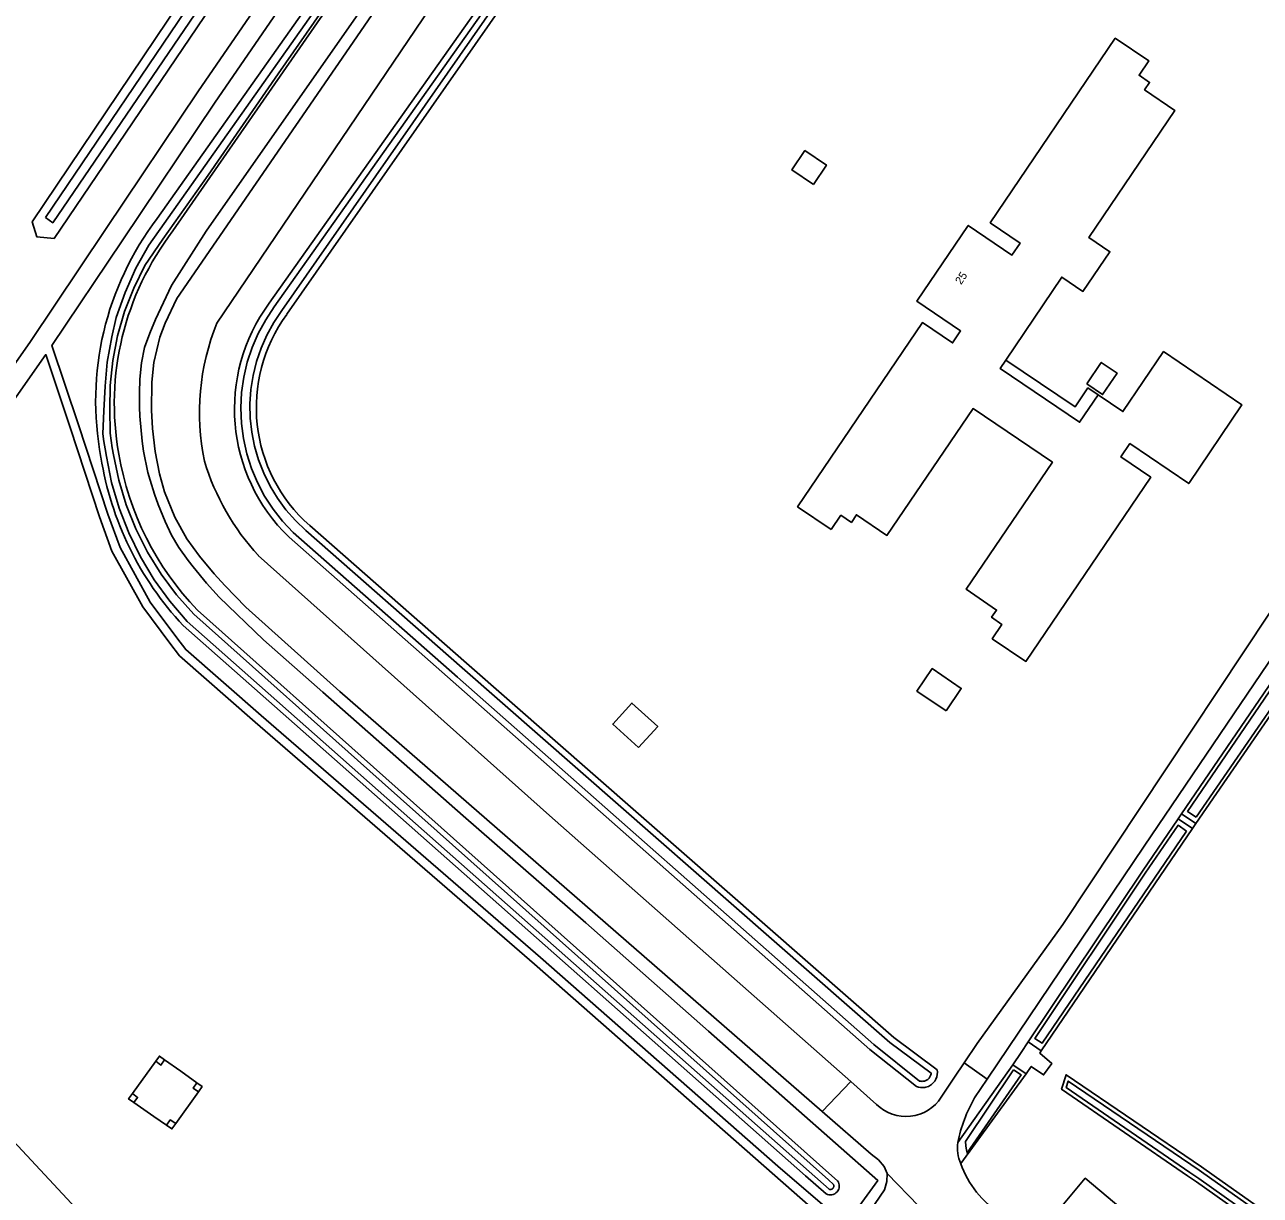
# Model space of a CAD drawing. Extents: x 158132 to 159658, y 385257 to 387209.
# Drawn here: x 159064.7 to 159219.1, y 385997.6 to 386143.9 of the extents above; entities that cross this region are included whole.
import ezdxf

# ---------------------------------------------------------------- set-up
doc = ezdxf.new("R2010")
doc.units = 0
for name, color, linetype in [('IMGEO_Berm_groen', 7, 'Continuous'), ('IMGEO_Erf', 7, 'Continuous'), ('IMGEO_Gemengd_bos', 7, 'Continuous'), ('IMGEO_Grasland_overig', 7, 'Continuous'), ('IMGEO_Groenvoorziening', 7, 'Continuous'), ('IMGEO_Hoogspanningsmast', 7, 'Continuous'), ('IMGEO_Pand', 7, 'Continuous'), ('IMGEO_Pand_nummerreeks', 7, 'Continuous'), ('IMGEO_Pand_overbouw', 7, 'Continuous'), ('IMGEO_Rijbaan_lokaal_gesloten', 7, 'Continuous'), ('IMGEO_Voetpad_onverhard', 7, 'Continuous'), ('IMGEO_Voetpad_open', 7, 'Continuous'), ('IMGEO_Waterloop', 7, 'Continuous')]:
    doc.layers.add(name, color=color, linetype=linetype)

msp = doc.modelspace()

# ---------------------------------------------------------------- linework, layer by layer
at = {"layer": 'IMGEO_Berm_groen'}
msp.add_lwpolyline([(159144.9, 386200.28), (159087.36, 386118.05), (159082.99, 386111.26), (159081, 386107), (159080.28, 386105.32), (159079.65, 386103.52), (159079.25, 386101.61), (159079.04, 386099.56), (159078.99, 386097.86), (159079.02, 386096.04), (159079.07, 386094.91), (159079.34, 386091.79), (159079.52, 386090.54), (159080.06, 386087.91), (159080.33, 386086.93), (159080.88, 386085.19), (159081.35, 386083.88), (159082.2, 386081.75), (159083.01, 386080.05), (159083.93, 386078.5), (159085.08, 386076.9), (159085.7, 386076.12), (159087.39, 386074.05), (159088.98, 386072.29), (159094.49, 386066.99), (159101.93, 386060.45), (159119.46, 386044.98), (159134.78, 386031.61), (159150.15, 386018.08), (159171.31, 385999.4), (159167.29, 385993.89)], dxfattribs=at)
at = {"layer": 'IMGEO_Erf'}
for points in [[(159154.57, 386192.95), (159095.21, 386109.04)], [(159097.43, 386107.66), (159155.21, 386190.47), (159156.49, 386192.28)], [(159119.88, 386064.08), (159100.3, 386081.25)], [(159097.7, 386079.81), (159118.22, 386061.71), (159170.28, 386015.78), (159176.12, 386011.15)], [(159178.72, 386013.24), (159173.29, 386017.26), (159119.88, 386064.08)]]:
    msp.add_lwpolyline(points, dxfattribs=at)
for centre, radius, start, end in [((159113.14, 386095.84), 22.26, 143.6506, 226.0684), ((159113.24, 386096.01), 19.63, 143.6275, 228.7695), ((159176.84, 386012.91), 1.91, 298.7399, 9.9074), ((159176.84, 386012.9), 1.89, 247.7201, 279.745), ((159176.85, 386012.88), 1.87, 279.3979, 298.8484)]:
    msp.add_arc(centre, radius, start, end, dxfattribs=at)
at = {"layer": 'IMGEO_Gemengd_bos'}
msp.add_lwpolyline([(159108.55, 386176.55), (159068.34, 386117.14), (159066.18, 386117.34), (159065.58, 386119.22), (159105.58, 386178.72)], dxfattribs=at)
at = {"layer": 'IMGEO_Grasland_overig'}
for points in [[(159026.34, 386043.95), (159128.6, 385934.11)], [(159078.12, 386010.26), (159081.04, 386014.3)], [(159082.15, 386014.49), (159084.16, 386013.05), (159086.18, 386011.61)], [(159086.37, 386010.49), (159083.53, 386006.51)], [(159082.4, 386006.31), (159080.81, 386007.42), (159078.31, 386009.15)]]:
    msp.add_lwpolyline(points, dxfattribs=at)
at = {"layer": 'IMGEO_Groenvoorziening'}
for points in [[(159143.41, 386207.64), (159081.22, 386119.64)], [(159083.19, 386118.08), (159144.68, 386206.73)], [(159211.05, 386044.02), (159246.68, 386095.71), (159262.72, 386118.74), (159262.51, 386120.37), (159261.9, 386120.78), (159261.17, 386121.26), (159260.05, 386120.35), (159247.53, 386101.26), (159209.27, 386045.25)], [(159109.81, 386049.69), (159086.26, 386070.68)], [(159084.47, 386068.77), (159108.37, 386047.64), (159162.26, 386000), (159164.82, 385997.74)], [(159166.27, 385999.37), (159165.56, 386000), (159109.81, 386049.69)], [(159208.83, 386044.6), (159204.36, 386038.05), (159190.08, 386016.72)], [(159191.71, 386015.61), (159210.63, 386043.41)], [(159188.18, 386013.88), (159181.3, 386004.16)], [(159181.66, 386001.51), (159189.85, 386012.75)], [(159240.08, 385978.69), (159211.12, 385999.23), (159210, 386000), (159194.26, 386010.81), (159194.82, 386012.63), (159211.74, 386001.12), (159213.33, 386000), (159240.84, 385980.57)]]:
    msp.add_lwpolyline(points, dxfattribs=at)
for centre, radius, start, end in [((159111.17, 386096.83), 37.64, 142.7073, 190.7888), ((159111.28, 386096.49), 35.42, 142.456, 190.2425), ((159112.88, 386096.34), 36.97, 189.5623, 223.9383), ((159113.52, 386096), 39.82, 188.9766, 223.1527), ((159165.36, 385998.72), 1.12, 241.0272, 35.9542)]:
    msp.add_arc(centre, radius, start, end, dxfattribs=at)
at = {"layer": 'IMGEO_Hoogspanningsmast'}
for points in [[(159081.04, 386014.3), (159081.5, 386014.95), (159082.15, 386014.49)], [(159081.04, 386014.3), (159081.69, 386013.84), (159082.15, 386014.49)], [(159086.18, 386011.61), (159085.71, 386010.96), (159086.37, 386010.49)], [(159086.18, 386011.61), (159086.83, 386011.14), (159086.37, 386010.49)], [(159078.31, 386009.15), (159077.65, 386009.61), (159078.12, 386010.26)], [(159078.31, 386009.15), (159078.77, 386009.79), (159078.12, 386010.26)], [(159083.53, 386006.51), (159082.86, 386006.97), (159082.4, 386006.31)], [(159083.53, 386006.51), (159083.06, 386005.86), (159082.4, 386006.31)]]:
    msp.add_lwpolyline(points, dxfattribs=at)
at = {"layer": 'IMGEO_Pand'}
for points in [[(159165.46, 386080.75), (159161.26, 386083.6), (159176.87, 386106.63), (159180.63, 386104.09), (159181.64, 386105.58), (159176.18, 386109.3), (159182.6, 386118.77), (159188.06, 386115.07), (159189.07, 386116.56), (159185.34, 386119.1), (159200.96, 386142.17), (159205.17, 386139.33), (159203.95, 386137.53), (159205.26, 386136.65), (159204.63, 386135.72), (159208.42, 386133.13), (159197.66, 386117.28), (159200.3, 386115.48), (159196.93, 386110.52), (159194.29, 386112.31), (159187.28, 386101.94), (159186.57, 386100.9), (159196.51, 386094.17), (159198.83, 386097.59), (159201.92, 386095.5), (159207.01, 386103), (159216.8, 386096.33), (159210.15, 386086.51), (159202.8, 386091.5), (159201.68, 386089.84), (159205.41, 386087.3), (159189.81, 386064.27), (159185.6, 386067.11), (159186.8, 386068.88), (159185.51, 386069.79), (159186.14, 386070.7), (159182.35, 386073.29), (159193.11, 386089.17), (159183.2, 386095.88), (159172.42, 386080.03), (159168.62, 386082.6), (159168, 386081.66), (159166.68, 386082.54), (159165.46, 386080.75)], [(159163.24, 386123.9), (159164.87, 386126.31), (159162.19, 386128.13), (159160.56, 386125.71), (159163.24, 386123.9)], [(159197.42, 386098.96), (159199.39, 386097.63), (159201.2, 386100.31), (159199.23, 386101.64), (159197.42, 386098.96)], [(159179.82, 386058.09), (159181.73, 386060.9), (159178.1, 386063.38), (159176.18, 386060.57), (159179.82, 386058.09)], [(159141.4, 386053.51), (159143.79, 386056.15), (159140.55, 386059.08), (159138.16, 386056.44), (159141.4, 386053.51)]]:
    msp.add_lwpolyline(points, dxfattribs=at)
at = {"layer": 'IMGEO_Pand_overbouw'}
msp.add_lwpolyline([(159187.28, 386101.94), (159186.57, 386100.9), (159196.51, 386094.17), (159198.83, 386097.59), (159197.55, 386098.46), (159195.94, 386096.08)], close=True, dxfattribs=at)
at = {"layer": 'IMGEO_Rijbaan_lokaal_gesloten'}
for points in [[(159146.86, 386200.68), (159128.76, 386175.21), (159083.68, 386109.62), (159082.2, 386106.57), (159081.56, 386104.81), (159080.8, 386101.62), (159080.54, 386099.16), (159080.52, 386095.68), (159080.65, 386093.4), (159080.97, 386090.53), (159081.51, 386087.71), (159082.15, 386085.46), (159083.44, 386082.3), (159084.94, 386079.61), (159086.49, 386077.43), (159088.34, 386075.22), (159089.68, 386073.77), (159092.32, 386071.08), (159104.06, 386060.51), (159164.35, 386008.03)], [(159088.69, 386106.57), (159122.73, 386156.88), (159125.6, 386160.77), (159130.26, 386167.41), (159134.25, 386173.17), (159139.74, 386181.11), (159145.82, 386189.71), (159151.33, 386197.56)], [(159182.09, 386014.12), (159183.73, 386016.54), (159194.42, 386031.4), (159229.89, 386084.81), (159246.98, 386109.91), (159257.08, 386124.85)], [(159258.33, 386120.06), (159249.31, 386107.22), (159204.57, 386041.21), (159184.98, 386012.08), (159184.96, 386012.05)], [(159167.9, 386011.78), (159130.24, 386045.01), (159093.86, 386077.52)], [(159182.09, 386014.12), (159180.88, 386012.31), (159179.23, 386009.8)], [(159184.96, 386012.05), (159182.09, 386014.12)], [(159167.9, 386011.78), (159164.35, 386008.03)], [(159171.14, 386008.92), (159167.9, 386011.78)], [(159183.39, 386009.74), (159184.96, 386012.05)], [(159164.35, 386008.03), (159170.46, 386002.71), (159171.37, 386001.97), (159172.1, 386001.17), (159172.48, 386000.3)], [(159168.48, 385992.87), (159172.11, 385998.23), (159172.43, 385999.29), (159172.48, 386000.3)], [(159172.48, 386000.3), (159176.42, 385996.19)]]:
    msp.add_lwpolyline(points, dxfattribs=at)
for centre, radius, start, end in [((159116.25, 386095.37), 29.75, 157.884, 191.7906), ((159116.46, 386098.25), 30.67, 196.9848, 222.5406), ((159174.83, 386012.63), 5.23, 225.1882, 327.2683), ((159199.25, 386000.61), 18.3, 150.0976, 168.8353), ((159186, 386003.45), 4.75, 171.426, 204.1255), ((159193.23, 386005.62), 12.28, 199.5694, 237.5869)]:
    msp.add_arc(centre, radius, start, end, dxfattribs=at)
at = {"layer": 'IMGEO_Voetpad_onverhard'}
for points in [[(159209.27, 386045.25), (159208.83, 386044.6)], [(159209.27, 386045.25), (159211.05, 386044.02)], [(159210.63, 386043.41), (159208.83, 386044.6)], [(159210.63, 386043.41), (159211.05, 386044.02)], [(159190.08, 386016.72), (159189.2, 386015.41), (159188.18, 386013.88)], [(159190.08, 386016.72), (159191.71, 386015.61)], [(159189.85, 386012.75), (159190.46, 386013.66), (159192.02, 386012.61), (159193.05, 386014.01), (159191.53, 386015.34), (159191.71, 386015.61)], [(159189.85, 386012.75), (159188.18, 386013.88)]]:
    msp.add_lwpolyline(points, dxfattribs=at)
at = {"layer": 'IMGEO_Voetpad_open'}
for points in [[(158987.13, 385983.76), (158985.38, 385985.66), (159024.58, 386045.84), (159026.86, 386049.34), (159065.31, 386104.15), (159074.76, 386118.24), (159086.39, 386135.58), (159115.48, 386177.93), (159137.05, 386210.07), (159143.29, 386219.37), (159143.28, 386220.9), (159143.27, 386223.44)], [(159167.29, 385993.89), (159158.79, 386001.21), (159129.11, 386027.28), (159094.2, 386057.51), (159084.8, 386065.76), (159083.69, 386067.21), (159080.36, 386071.69), (159076.58, 386078.52), (159075.04, 386082.7), (159071.38, 386093.86), (159068.07, 386103.78), (159076.84, 386116.84), (159088.46, 386134.17), (159117.55, 386176.52), (159139.13, 386208.67), (159145.27, 386217.83), (159146.45, 386217.87)], [(159026.34, 386043.95), (159028.94, 386047.93), (159067.29, 386102.62), (159070.33, 386093.52), (159073.99, 386082.33), (159075.57, 386078.05), (159079.43, 386071.09), (159082.8, 386066.54), (159083.99, 386064.99), (159093.47, 386056.67), (159128.38, 386026.44), (159167.77, 385991.84)], [(159202.32, 385992.98), (159201.51, 385993.67), (159201.75, 385993.96), (159202.69, 385995.07), (159197.23, 385999.68), (159192.41, 385993.96), (159198.68, 385988.67), (159202.32, 385992.98)]]:
    msp.add_lwpolyline(points, dxfattribs=at)
at = {"layer": 'IMGEO_Waterloop'}
for points in [[(159154.6, 386190.97), (159096.79, 386108.12), (159095.8, 386106.64), (159094.93, 386105.07), (159094.21, 386103.44), (159093.64, 386101.75), (159093.21, 386100.02), (159092.94, 386098.26), (159092.82, 386096.48), (159092.86, 386094.69), (159093.05, 386092.92), (159093.4, 386091.17), (159093.9, 386089.46), (159094.54, 386087.79), (159095.33, 386086.2), (159096.26, 386084.67), (159097.31, 386083.23), (159098.49, 386081.89), (159099.78, 386080.66), (159119.36, 386063.49), (159172.8, 386016.65), (159177.96, 386012.83), (159177.94, 386012.73), (159177.92, 386012.63), (159177.89, 386012.53), (159177.85, 386012.44), (159177.81, 386012.35), (159177.75, 386012.26), (159177.69, 386012.18), (159177.62, 386012.11), (159177.55, 386012.04), (159177.46, 386011.98), (159177.38, 386011.93), (159177.29, 386011.89), (159177.21, 386011.86), (159177.12, 386011.83), (159177.03, 386011.81), (159176.93, 386011.8), (159176.82, 386011.79), (159176.72, 386011.8), (159176.61, 386011.82), (159176.51, 386011.84), (159170.79, 386016.39), (159118.74, 386062.3), (159098.23, 386080.39), (159096.9, 386081.79), (159095.71, 386083.3), (159094.65, 386084.92), (159093.75, 386086.62), (159093, 386088.4), (159092.41, 386090.24), (159091.99, 386092.12), (159091.74, 386094.03), (159091.67, 386095.96), (159091.76, 386097.89), (159092.03, 386099.8), (159092.48, 386101.68), (159093.08, 386103.51), (159093.85, 386105.28), (159094.78, 386106.97), (159095.85, 386108.58), (159155.18, 386192.43)], [(159067.24, 386119.76), (159105.86, 386176.8), (159106.98, 386176.07), (159068.16, 386119.1), (159067.24, 386119.76)], [(159079.67, 386113.76), (159078.29, 386110.93), (159077.15, 386108), (159076.28, 386104.98), (159075.68, 386101.9), (159075.34, 386098.77), (159075.29, 386095.82), (159075.36, 386092.79), (159075.47, 386091.88), (159075.59, 386090.98), (159075.74, 386090.08), (159076.42, 386086.92), (159077.36, 386083.83), (159078.56, 386080.83), (159080.02, 386077.95), (159081.71, 386075.2), (159083.64, 386072.61), (159085.78, 386070.19), (159109.35, 386049.18), (159165.11, 385999.49), (159165.74, 385998.92), (159165.76, 385998.89), (159165.77, 385998.85), (159165.78, 385998.82), (159165.79, 385998.78), (159165.79, 385998.74), (159165.79, 385998.71), (159165.79, 385998.67), (159165.78, 385998.63), (159165.77, 385998.59), (159165.76, 385998.56), (159165.75, 385998.52), (159165.73, 385998.49), (159165.71, 385998.46), (159165.68, 385998.43), (159165.66, 385998.4), (159165.63, 385998.38), (159165.6, 385998.36), (159165.57, 385998.34), (159165.53, 385998.32), (159165.5, 385998.31), (159165.46, 385998.3), (159165.43, 385998.29), (159165.39, 385998.29), (159165.35, 385998.29), (159165.31, 385998.29), (159165.28, 385998.29), (159165.24, 385998.3), (159165.2, 385998.31), (159162.71, 386000.52), (159108.83, 386048.15), (159084.95, 386069.26), (159082.78, 386071.79), (159080.83, 386074.49), (159079.12, 386077.34), (159077.66, 386080.34), (159076.46, 386083.44), (159075.52, 386086.64), (159074.87, 386089.91), (159074.7, 386090.84), (159074.56, 386091.78), (159074.44, 386092.72), (159074.54, 386095.61), (159074.72, 386098.68), (159074.96, 386101.7), (159075.56, 386104.83), (159076.11, 386107.27), (159077.2, 386110.39), (159078.56, 386113.41), (159080.19, 386116.29), (159082.08, 386119.01), (159107.02, 386154.3)], [(159104.4, 386149.29), (159096.35, 386137.72), (159087.61, 386125.03), (159081.94, 386117.04), (159079.67, 386113.76)], [(159211.07, 386044.81), (159210.01, 386045.54), (159247.89, 386101.02), (159260.38, 386120.05), (159261.2, 386120.71), (159261.64, 386120.42), (159262.1, 386120.12), (159262.26, 386118.85), (159246.32, 386095.96), (159211.07, 386044.81)], [(159209.88, 386043.08), (159191.82, 386016.56), (159190.91, 386017.17), (159204.72, 386037.8), (159208.82, 386043.81), (159209.88, 386043.08)], [(159188.27, 386013.23), (159189.21, 386012.6), (159182.45, 386002.86), (159182.38, 386003.18), (159182.3, 386003.72), (159182.26, 386004.26), (159188.27, 386013.23)], [(159241.19, 385979.71), (159241.11, 385979.4), (159240.95, 385979.2), (159240.5, 385979.01), (159211.41, 385999.64), (159210.28, 386000.42), (159194.85, 386011.02), (159195.1, 386011.83), (159211.46, 386000.7), (159213.04, 385999.59), (159241.19, 385979.71)]]:
    msp.add_lwpolyline(points, dxfattribs=at)

# ---------------------------------------------------------------- texts
at = {"layer": 'IMGEO_Pand_nummerreeks'}
msp.add_text('25', height=1, rotation=55.8347, dxfattribs=at).set_placement((159181.7, 386111.3))

doc.saveas('drawing.dxf')
